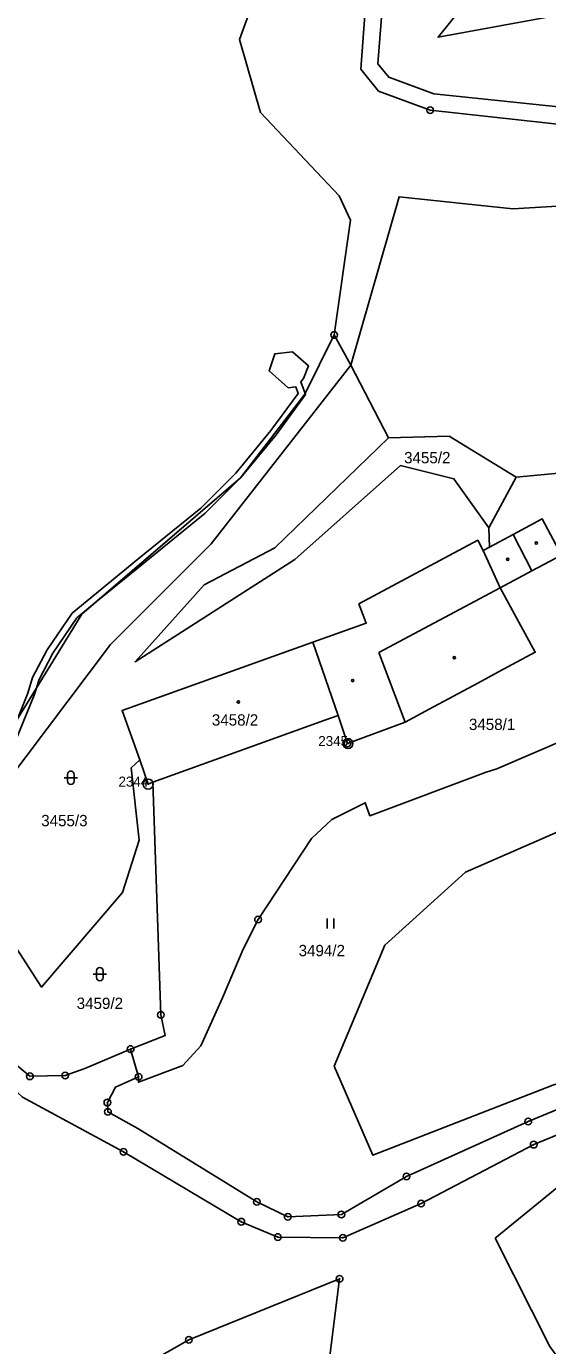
# Model space of a CAD drawing. Extents: x -644096 to -634268, y -1141430 to -1133463.
# Drawn here: x -641546.1 to -641468, y -1138250.7 to -1138053 of the extents above; entities that cross this region are included whole.
import ezdxf

# ---------------------------------------------------------------- set-up
doc = ezdxf.new("R2010")
doc.units = 0
for name, color, linetype in [('_CIVIL_CONSTRUCTION', 7, 'Continuous'), ('B_Hranice _3D', 7, 'Continuous'), ('M_Svah_Nasyp', 7, 'Continuous'), ('M_Svah_Zarez', 7, 'Continuous'), ('svrsek_osa_sjezdy', 7, 'Continuous'), ('svrsek_osa_VRT', 7, 'Continuous'), ('terminal_VRT', 7, 'Continuous')]:
    doc.layers.add(name, color=color, linetype=linetype)

msp = doc.modelspace()

# ---------------------------------------------------------------- linework, layer by layer
at = {"layer": '_CIVIL_CONSTRUCTION'}
for centre, radius in [((-641485.59, -1138065.55), 0.5), ((-641485.59, -1138065.55), 0.0303), ((-641499.97, -1138099.24), 0.5), ((-641499.97, -1138099.24), 0.0303), ((-641497.91, -1138160.47), 0.75), ((-641497.98, -1138160.44), 0.5), ((-641497.98, -1138160.44), 0.0303), ((-641497.91, -1138160.47), 0.03), ((-641527.87, -1138166.54), 0.75), ((-641527.87, -1138166.54), 0.03), ((-641511.39, -1138186.83), 0.5), ((-641511.39, -1138186.83), 0.0303), ((-641525.98, -1138201.13), 0.5), ((-641525.98, -1138201.13), 0.0303), ((-641530.5, -1138206.25), 0.5), ((-641530.5, -1138206.25), 0.0303), ((-641545.6, -1138210.34), 0.5), ((-641545.6, -1138210.34), 0.0303), ((-641540.31, -1138210.22), 0.5), ((-641540.31, -1138210.22), 0.0303), ((-641529.3, -1138210.41), 0.5), ((-641529.3, -1138210.41), 0.0303), ((-641533.99, -1138214.28), 0.5), ((-641533.99, -1138214.28), 0.0303), ((-641533.9, -1138215.65), 0.5), ((-641533.9, -1138215.65), 0.0303), ((-641470.87, -1138217.1), 0.5), ((-641470.87, -1138217.1), 0.0303), ((-641470.06, -1138220.58), 0.5), ((-641470.06, -1138220.58), 0.0303), ((-641531.58, -1138221.66), 0.5), ((-641531.58, -1138221.66), 0.0303), ((-641489.12, -1138225.34), 0.5), ((-641489.12, -1138225.34), 0.0303), ((-641511.58, -1138229.14), 0.5), ((-641511.58, -1138229.14), 0.0303), ((-641498.9, -1138231.05), 0.5), ((-641486.94, -1138229.41), 0.5), ((-641486.94, -1138229.41), 0.0303), ((-641513.9, -1138232.13), 0.5), ((-641513.9, -1138232.13), 0.0303), ((-641506.94, -1138231.39), 0.5), ((-641506.94, -1138231.39), 0.0303), ((-641498.9, -1138231.05), 0.0303), ((-641508.42, -1138234.43), 0.5), ((-641508.42, -1138234.43), 0.0303), ((-641498.69, -1138234.54), 0.5), ((-641498.69, -1138234.54), 0.0303), ((-641499.16, -1138240.68), 0.5), ((-641499.16, -1138240.68), 0.0303), ((-641521.77, -1138249.82), 0.5), ((-641521.77, -1138249.82), 0.0303)]:
    msp.add_circle(centre, radius, dxfattribs=at)
at = {"layer": 'B_Hranice _3D'}
for points in [[(-641547.43, -1138156.68), (-641544.63, -1138152.15), (-641544.27, -1138150.95), (-641542.15, -1138146.92), (-641538.55, -1138141.62), (-641535.9, -1138139.45), (-641514.03, -1138120.63), (-641504.38, -1138108.13), (-641504.33, -1138108.03), (-641504.96, -1138106.27), (-641504.59, -1138105.77), (-641503.83, -1138103.84), (-641506.22, -1138101.77), (-641508.88, -1138102.06), (-641509.74, -1138104.63), (-641506.9, -1138107.14), (-641505.75, -1138107.02), (-641505.4, -1138108), (-641509.48, -1138113.56), (-641514.71, -1138119.94), (-641519.98, -1138125.18), (-641529.4, -1138132.84), (-641539.29, -1138140.94), (-641543.01, -1138146.4), (-641545.21, -1138150.57), (-641545.9, -1138152.9)], [(-641535.9, -1138139.45), (-641528.76, -1138133.62), (-641519.32, -1138125.92), (-641513.97, -1138120.62), (-641508.68, -1138114.18), (-641504.28, -1138108.16), (-641504.33, -1138108.03), (-641504.38, -1138108.13), (-641514.03, -1138120.63)], [(-641559.63, -1138187.75), (-641559.29, -1138187.73), (-641558.52, -1138186.57), (-641557.14, -1138182.94), (-641554.09, -1138174.71), (-641552.56, -1138171.36), (-641552.61, -1138170.89), (-641551.93, -1138169.99), (-641547.69, -1138159.97), (-641544.96, -1138153.24), (-641544.63, -1138152.15), (-641547.43, -1138156.68), (-641552.16, -1138168.08), (-641555.01, -1138174.33), (-641555.67, -1138176.1), (-641555.6, -1138176.41)]]:
    msp.add_lwpolyline(points, close=True, dxfattribs=at)
at = {"layer": 'M_Svah_Nasyp'}
for p, q in [((-641473.14, -1138129.14), (-641470.32, -1138134.58)), ((-641477.62, -1138131.53), (-641475.09, -1138137.13)), ((-641493.26, -1138146.83), (-641475.09, -1138137.13)), ((-641503.2, -1138145.29), (-641499.38, -1138156.25)), ((-641489.34, -1138157.27), (-641493.26, -1138146.83))]:
    msp.add_line(p, q, dxfattribs=at)
at = {"layer": 'M_Svah_Zarez'}
for centre in [(-641469.68, -1138130.43), (-641473.95, -1138132.84), (-641481.96, -1138147.61), (-641497.18, -1138151.02), (-641514.33, -1138154.22)]:
    msp.add_circle(centre, 0.175, dxfattribs=at)
at = {"layer": 'svrsek_osa_sjezdy'}
for p, q in [((-641539.97, -1138165.09), (-641539.97, -1138166.09)), ((-641538.97, -1138166.09), (-641538.97, -1138165.09)), ((-641540.47, -1138165.59), (-641538.47, -1138165.59)), ((-641501.03, -1138188.21), (-641501.03, -1138186.71)), ((-641500.03, -1138188.21), (-641500.03, -1138186.71)), ((-641536.12, -1138195.02), (-641534.12, -1138195.02)), ((-641535.62, -1138194.52), (-641535.62, -1138195.52)), ((-641534.62, -1138195.52), (-641534.62, -1138194.52))]:
    msp.add_line(p, q, dxfattribs=at)
for centre, start, end in [((-641539.47, -1138165.09), 0, 180), ((-641539.47, -1138166.09), 180, 359.9879), ((-641535.12, -1138194.52), 0, 180), ((-641535.12, -1138195.52), 180, 359.9879)]:
    msp.add_arc(centre, 0.5, start, end, dxfattribs=at)
at = {"layer": 'terminal_VRT'}
for p, q in [((-641499.97, -1138099.24), (-641497.47, -1138103.75)), ((-641497.47, -1138103.75), (-641491.85, -1138114.66)), ((-641472.7, -1138120.54), (-641476.8, -1138128.16)), ((-641476.8, -1138128.16), (-641476.66, -1138131.02)), ((-641530.5, -1138206.25), (-641529.3, -1138210.41))]:
    msp.add_line(p, q, dxfattribs=at)
for points in [[(-641370.69, -1138086.45), (-641384.8, -1138065.03), (-641394.24, -1138057.89), (-641414.27, -1138050.93), (-641431.86, -1138047.07), (-641445.19, -1138046.92), (-641455.94, -1138049.41), (-641484.39, -1138054.62), (-641472.41, -1138039.72), (-641465.08, -1138034.31), (-641450.28, -1138030), (-641455.8, -1138019.55), (-641462.41, -1138015.68), (-641462.33, -1137970.13)], [(-641378.25, -1138084.34), (-641385.85, -1138082.21), (-641419.6, -1138072.79), (-641485.59, -1138065.55), (-641493.32, -1138062.69), (-641495.98, -1138059.38), (-641493.5, -1138025.57)], [(-641378.25, -1138084.34), (-641395.46, -1138072.42), (-641485.01, -1138063.1), (-641491.8, -1138060.59), (-641493.41, -1138058.58), (-641490.88, -1138026.24)], [(-641506.38, -1138033.52), (-641514.19, -1138054.98), (-641511, -1138065.92), (-641499.25, -1138078.39), (-641497.55, -1138082.01), (-641499.97, -1138099.24)], [(-641497.47, -1138103.75), (-641490.24, -1138078.52), (-641473.17, -1138080.31), (-641452.33, -1138079.07), (-641447.95, -1138075.37), (-641421.8, -1138077.33), (-641408.77, -1138081.55), (-641404.24, -1138089.31), (-641401.7, -1138102.44), (-641411.58, -1138105.87)], [(-641499.97, -1138099.24), (-641504.38, -1138108.13), (-641514.03, -1138120.63), (-641537.8, -1138141.09), (-641556.68, -1138171.65), (-641555.6, -1138176.41), (-641560.08, -1138189.01)], [(-641497.47, -1138103.75), (-641518.43, -1138130.55), (-641533.52, -1138145.64), (-641552.61, -1138170.89), (-641551.92, -1138177.29), (-641550.84, -1138186.18), (-641543.88, -1138196.97), (-641531.7, -1138182.81), (-641529.23, -1138174.94), (-641530.42, -1138164.13), (-641529.13, -1138162.92)], [(-641411.58, -1138105.87), (-641421.72, -1138109.68), (-641436.64, -1138112.06), (-641440.53, -1138113.21), (-641446.42, -1138119.87), (-641457.91, -1138119.16), (-641472.7, -1138120.54)], [(-641491.85, -1138114.66), (-641508.89, -1138131.14), (-641519.45, -1138136.67), (-641529.83, -1138148.22), (-641505.86, -1138132.9), (-641490.04, -1138118.81), (-641482.01, -1138120.79), (-641476.8, -1138128.16)], [(-641491.85, -1138114.66), (-641482.75, -1138114.4), (-641472.7, -1138120.54)], [(-641476.66, -1138131.02), (-641473.14, -1138129.14), (-641468.77, -1138126.81), (-641465.89, -1138132.22)], [(-641529.13, -1138162.92), (-641531.77, -1138155.54), (-641503.2, -1138145.29), (-641495.16, -1138142.41), (-641496.26, -1138139.52), (-641478.44, -1138130.01), (-641477.62, -1138131.53), (-641476.66, -1138131.02)], [(-641465.89, -1138132.22), (-641470.32, -1138134.58), (-641475.09, -1138137.13), (-641469.82, -1138146.79), (-641475.31, -1138149.74), (-641478.44, -1138151.42), (-641485.75, -1138155.34), (-641489.34, -1138157.27), (-641497.98, -1138160.44), (-641499.38, -1138156.25), (-641501.39, -1138156.97), (-641527.15, -1138166.28)], [(-641529.3, -1138210.41), (-641529.3, -1138211.22), (-641522.69, -1138208.7), (-641519.99, -1138205.77), (-641516.7, -1138198.57), (-641513.6, -1138191.29), (-641511.39, -1138186.83), (-641503.37, -1138174.68), (-641500.33, -1138171.87), (-641495.31, -1138169.34), (-641494.63, -1138171.29), (-641477.19, -1138164.75), (-641475.59, -1138164.28), (-641438.16, -1138148.19), (-641437.59, -1138147.85)], [(-641427.84, -1138169.35), (-641427.05, -1138168.41), (-641435.78, -1138160.42), (-641439.2, -1138160.33), (-641442.38, -1138161.54), (-641445.13, -1138163.2), (-641452.26, -1138167.52), (-641480.29, -1138179.74), (-641492.37, -1138190.69), (-641499.98, -1138208.8), (-641494.18, -1138222.14), (-641467.21, -1138211.65), (-641426.73, -1138199.25), (-641424.78, -1138200.2), (-641423.18, -1138199.47), (-641419.92, -1138197.98), (-641417.61, -1138193.63), (-641438.22, -1138162.45), (-641436, -1138162.31), (-641427.84, -1138169.35)], [(-641529.13, -1138162.92), (-641527.87, -1138166.54), (-641527.15, -1138166.28)], [(-641527.15, -1138166.28), (-641525.98, -1138201.13), (-641525.3, -1138204.23), (-641530.5, -1138206.25)], [(-641566.52, -1138189.97), (-641556.86, -1138200.96), (-641545.6, -1138210.34), (-641540.31, -1138210.22), (-641537.36, -1138209.19), (-641530.5, -1138206.25)], [(-641529.3, -1138210.41), (-641532.77, -1138211.96), (-641533.99, -1138214.28), (-641533.9, -1138215.65), (-641529.43, -1138218.18), (-641511.58, -1138229.14), (-641506.94, -1138231.39), (-641498.9, -1138231.05), (-641489.12, -1138225.34), (-641470.87, -1138217.1), (-641457.32, -1138211.53), (-641440.72, -1138205.56), (-641422.51, -1138200.58), (-641419.01, -1138199.15), (-641412.96, -1138196.06)], [(-641420.78, -1138203.82), (-641439.92, -1138208.86), (-641456.3, -1138214.9), (-641470.06, -1138220.58), (-641486.94, -1138229.41), (-641498.69, -1138234.54), (-641508.42, -1138234.43), (-641513.9, -1138232.13), (-641531.58, -1138221.66), (-641546.69, -1138213.48), (-641548.98, -1138211.35), (-641550.26, -1138210.33)], [(-641451.04, -1138217.93), (-641460.09, -1138221.75), (-641475.83, -1138234.6), (-641467.62, -1138250.82), (-641460.82, -1138260.06), (-641444.44, -1138268.99)], [(-641587.4, -1138294.08), (-641567.86, -1138276.46), (-641537.66, -1138258.88), (-641521.77, -1138249.82), (-641499.16, -1138240.68), (-641500.73, -1138253.04)]]:
    msp.add_lwpolyline(points, dxfattribs=at)

# ---------------------------------------------------------------- texts
at = {"layer": '_CIVIL_CONSTRUCTION'}
for s, p in [('2345', (-641502.36, -1138160.84)), ('2344', (-641532.32, -1138166.92))]:
    msp.add_text(s, height=1.5, dxfattribs=at).set_placement(p)
at = {"layer": 'svrsek_osa_VRT'}
for s, p in [('3455/2', (-641489.49, -1138118.47)), ('3458/2', (-641518.32, -1138157.78)), ('3458/1', (-641479.77, -1138158.44)), ('3455/3', (-641543.91, -1138172.86)), ('3494/2', (-641505.31, -1138192.34)), ('3459/2', (-641538.59, -1138200.25))]:
    msp.add_text(s, height=1.7, dxfattribs=at).set_placement(p)

doc.saveas('drawing.dxf')
